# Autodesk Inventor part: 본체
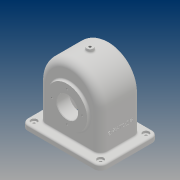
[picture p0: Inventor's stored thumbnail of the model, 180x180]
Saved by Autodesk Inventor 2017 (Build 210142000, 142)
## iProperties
Part Number: 본체
Material: 일반
Document SubType Name: Modeling
Designer: 20
Density: 1 g/cm^3
Appearance: 기본값
Author: 20
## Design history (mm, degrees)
sketch "스케치2"
  geometry: L1 (58, 0)-(58, -78); L2 (-58, 0)-(-58, -78); L3 (58, -78)-(-58, -78); A1 r 58 centre (0, 0) between (58, 0) and (-58, 0); 1 further point
  constraints: 6 end point, 2 point on circle, 2 tangent, 2 vertical, 1 centre point, 1 coincident, 1 horizontal
  dimensions: "d1" = 116 diameter of A1; "d2" = 78 distance of L2.start L2.end
extrude "돌출1" new body sketch "스케치2" stored distance "d3" = 77; taper "d4" = 0 deg
sketch "스케치9"
  geometry: L1 (-58, -78)-(58, -78) reference; C1 r 38 at (0, -13); 1 further point
  constraints: 1 centre point, 1 vertical alignment
  dimensions: "d30" = 76 diameter of C1; "d31" = 65 distance from line of L1 C1.centre
extrude "돌출4" join sketch "스케치9" distance "d32" = 5; taper "d33" = 0 deg
sketch "스케치11"
  geometry: L1 (58, 78)-(-58, 78) reference; C1 r 38 at (0, 13); 1 further point
  constraints: 1 centre point, 1 vertical alignment
  dimensions: "d37" = 76 diameter of C1; "d38" = 65 distance from line of L1 C1.centre
extrude "돌출6" join sketch "스케치11" distance "d39" = 10; taper "d40" = 0 deg
sketch "스케치12"
  geometry: C1 r 38 at (0, 0) reference; C2 r 20 at (0, 0); 1 further point
  constraints: 1 centre point, 1 coincident
  dimensions: "d41" = 40 diameter of C2
extrude "돌출7" cut sketch "스케치12" distance "d42" = 15; taper "d43" = 0 deg
sketch "스케치16"
  geometry: L1 (-58, -78)-(58, -78) reference; L2 (52, 0)-(52, -78); L3 (-52, 0)-(-52, -78); A1 r 52 centre (0, 0) between (52, 0) and (-52, 0); A2 r 58 centre (0, 0) between (58, 0) and (-58, 0) reference; 2 further points
  constraints: 4 end point, 3 point on circle, 2 point on line, 2 tangent, 2 vertical, 2 vertical alignment, 1 centre point
  dimensions: "d62" = 104 diameter of A1; "d63" = 78 distance from line of L1 A1.centre; "d64" = 78 distance of L3.start L3.end (derived)
extrude "돌출8" cut sketch "스케치16" stored distance "d65" = 67; taper "d66" = 0 deg
sketch "스케치18"
  geometry: L1 (-33.5, 26.747)-(-19.5, 15); L2 (-19.5, 15)-(-19.5, -13); L3 (-64.042, -13)-(64.042, -13); L4 (33.5, -78)-(-33.5, -78) reference; L5 (-33.5, 26.747)-(-33.5, -13); L6 (-38.5, 58)-(-38.5, 0) reference; L7 (-43.5, 25)-(-43.5, -51) reference; L8 (-33.5, -13)-(-19.5, -13); 2 further points
  constraints: 10 end point, 2 horizontal, 2 vertical, 1 midpoint, 1 point on line, 1 vertical alignment
  dimensions: "d67" = 65 distance between parallel lines of L4 L3; "d68" = 5 distance between parallel lines of L6 L5; "d69" = 24 distance between parallel lines of L7 L2; "d70" = 50 deg angle of L1 L2; "d71" = 56 diameter of L1.end L3
revolve "회전3" sketch "스케치18" stored, may be unused: angle "d72" = 90 deg
sketch "스케치19"
  geometry: L1 (-58, -65)-(58, -65) reference; C1 r 20 at (0, 0); 1 further point
  constraints: 1 centre point, 1 vertical alignment
  dimensions: "d73" = 40 diameter of C1; "d74" = 65 distance from line of L1 C1.centre
extrude "돌출9" cut sketch "스케치19" distance "d75" = 24; taper "d76" = 0 deg
sketch "스케치20"
  geometry: L1 (133, -93.5)-(-17, -93.5); L2 (-17, -93.5)-(-17, 16.5); L3 (-17, 16.5)-(133, 16.5); L4 (133, 16.5)-(133, -93.5); L5 (133, -93.5)-(-17, 16.5); L6 (-17, -93.5)-(133, 16.5); L7 (6, -5)-(6, -72) reference; L8 (6, -72)-(110, -72) reference; L9 (110, -72)-(110, -5) reference; L10 (110, -5)-(6, -5) reference; 1 further point
  constraints: 12 end point, 2 midpoint, 2 parallel, 1 horizontal, 1 perpendicular
  dimensions: "d77" = 110 distance of L1.end L2.end; "d78" = 150 distance of L2.end L3.end
extrude "돌출10" join sketch "스케치20" distance "d79" = 10; taper "d80" = 0 deg
fillet "모깎기1" dims "d81" = 12
hole "구멍1" diameter "d84" = 5; stored, may be unused: countersink angle "d88" = 90 deg, drill point angle "d90" = 118 deg; dims "d82" = 10, "d83" = 10, "d85" = 6, "d86" = 12, "d87" = 4, "d89" = 8
hole "구멍2" diameter "d93" = 5; stored, may be unused: countersink angle "d97" = 90 deg, drill point angle "d99" = 118 deg; dims "d91" = 10, "d92" = 10, "d94" = 6, "d95" = 12, "d96" = 4, "d98" = 8
hole "구멍3" diameter "d102" = 5; stored, may be unused: countersink angle "d106" = 90 deg, drill point angle "d108" = 118 deg; dims "d100" = 10, "d101" = 10, "d103" = 6, "d104" = 12, "d105" = 4, "d107" = 8
hole "구멍4" diameter "d111" = 5; stored, may be unused: countersink angle "d115" = 90 deg, drill point angle "d117" = 118 deg; dims "d109" = 10, "d110" = 10, "d112" = 6, "d113" = 12, "d114" = 4, "d116" = 8
node "작업 평면1"
sketch "스케치21"
  geometry: C1 r 6 at (0, 0); 1 further point
  constraints: 1 centre point, 1 coincident
  dimensions: "d119" = 12 diameter of C1
extrude "돌출11" join sketch "스케치21" stored distance "d120" = 10; taper "d121" = 5 deg
hole "구멍5" diameter "d124" = 4.459; stored, may be unused: countersink angle "d128" = 90 deg, drill point angle "d130" = 118 deg; dims "d122" = 10, "d123" = 10, "d125" = 10, "d126" = 12, "d127" = 4, "d129" = 12.8
sketch "스케치22"
  geometry: C1 r 20 at (0, 0) reference; 2 further points
  constraints: 1 vertical alignment
  dimensions: "d131" = 29 distance of C1.centre point (0, -29)
hole "구멍6" sketch "스케치22" at (0, -29) diameter "d132" = 3.242; stored, may be unused: countersink angle "d136" = 90 deg, drill point angle "d138" = 118 deg; dims "d133" = 8, "d134" = 12, "d135" = 4, "d137" = 10
sketch "스케치23"
  geometry: C1 r 20 at (0, 0) reference; 2 further points
  constraints: 1 vertical alignment
  dimensions: "d142" = 29 distance of C1.centre point (0, 29)
hole "구멍7" sketch "스케치23" at (0, 29) diameter "d143" = 3.242; stored, may be unused: countersink angle "d147" = 90 deg, drill point angle "d149" = 118 deg; dims "d144" = 8, "d145" = 12, "d146" = 4, "d148" = 10
fillet "모깎기2" dims "d153" = 8
chamfer "모따기1" distance "d154" = 1; stored, may be unused: second distance "d155" = 2, angle "d156" = 45 deg
fillet "모깎기3" dims "d157" = 13
fillet "모깎기4" dims "d158" = 3
fillet "모깎기5" dims "d159" = 3
fillet "모깎기6" dims "d160" = 3
fillet "모깎기7" dims "d161" = 3
sketch "스케치24"
  geometry: L1 (65, 64)-(0, 64) reference; L2 (78, -17.5)-(78, 68.5) reference; 2 further points
  constraints: 1 other
  dimensions: "d162" = 38.5 distance from line of L1 point (38, 25.5); "d163" = 40 distance from line of L2 point (38, 25.5)
feature "엠보싱1" sketch "스케치24" dims "d1" = 116, "d2" = 78, "d164" = 0.5, "d165" = 0
node "솔리드1"
pattern_circular "원형 패턴1" dims angle "d140" = 360 deg
pattern_circular "원형 패턴2" dims angle "d151" = 360 deg
node "투영된 루프3"
other parameters: "d118" = 64
